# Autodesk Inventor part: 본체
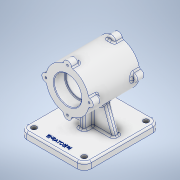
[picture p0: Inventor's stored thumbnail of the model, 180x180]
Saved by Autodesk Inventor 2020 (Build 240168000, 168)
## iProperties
Created: 2022-11
Part Number: 본체
Material: 알루미늄 6061
Document SubType Name: Modeling
Designer: Owner
Density: 2.7 g/cm^3
Appearance: 알루미늄 - 평지
Mass: 1215.39 g
Surface Area: 796.917 cm^2
Volume: 450.145 cm^3
Author: Owner
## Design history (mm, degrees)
sketch "스케치1"
  geometry: C1 r 7 at (0, 37); C2 r 7 at (37, 0); C3 r 7 at (0, -37); C4 r 7 at (-37, 0); A1 r 37 centre (0, 0) between (0, 37) and (37, 0); 9 further points
  constraints: 5 centre point, 4 point on circle, 2 horizontal alignment, 2 vertical alignment, 1 coincident
  dimensions: "d0" = 74 diameter of A1; "d1" = 14 diameter of C1; "d2" = 14 diameter of C2; "d3" = 14 diameter of C3; "d4" = 14 diameter of C4
extrude "돌출1" new body sketch "스케치1" stored distance "d5" = 87; taper "d6" = 0 deg
sketch "스케치2"
  geometry: A1 r 37 centre (0, 0) between (36.338, 6.969) and (6.969, 36.338) reference; 2 further points
  constraints: 1 coincident
hole "구멍1" sketch "스케치2" at (0, 0) diameter "d7" = 42; stored, may be unused: countersink angle "d11" = 90 deg, drill point angle "d13" = 0 deg; dims "d8" = 8, "d9" = 47, "d10" = 19, "d12" = 68
sketch "스케치3"
  geometry: A1 r 37 centre (0, 0) between (36.338, 6.969) and (6.969, 36.338) reference; 2 further points
  constraints: 1 coincident
hole "구멍2" sketch "스케치3" at (0, 0) diameter "d14" = 47; stored, may be unused: countersink angle "d18" = 90 deg, drill point angle "d20" = 0 deg; dims "d15" = 8, "d16" = 47, "d17" = 19, "d19" = 19
sketch "스케치4"
  geometry: 1 further point
node "작업 평면1"
sketch "스케치11"
  geometry: L1 (-37, -43.5)-(37, -43.5) reference; L2 (37, 43.5)-(-37, 43.5) reference; L3 (-55, -60)-(55, -60); L4 (55, -60)-(55, 70); L5 (55, 70)-(-55, 70); L6 (-55, 70)-(-55, -60); 2 further points
  constraints: 8 end point, 2 parallel, 1 horizontal, 1 midpoint, 1 perpendicular, 1 vertical alignment
  dimensions: "d49" = 130 distance of L3.end L4.end; "d50" = 70 distance from line of L5 point (0, 0); "d51" = 110 distance of L3.start L3.end
extrude "돌출3" join sketch "스케치11" distance "d52" = 12; taper "d53" = 0 deg
fillet "모깎기2" dims "d54" = 12
sketch "스케치12"
  geometry: 1 further point
sketch "스케치13"
  geometry: A1 r 12 centre (-43, -58) between (-55, -58) and (-43, -70) reference; 2 further points
  constraints: 1 coincident
hole "구멍6" sketch "스케치13" at (-43, -58) diameter "d55" = 9; stored, may be unused: countersink angle "d59" = 90 deg, drill point angle "d61" = 0 deg; dims "d56" = 8, "d57" = 47, "d58" = 19, "d60" = 19
sketch "스케치14"
  geometry: A1 r 12 centre (43, -58) between (43, -70) and (55, -58) reference; 2 further points
  constraints: 1 coincident
hole "구멍7" sketch "스케치14" at (43, -58) diameter "d62" = 9; stored, may be unused: countersink angle "d66" = 90 deg, drill point angle "d68" = 0 deg; dims "d63" = 8, "d64" = 47, "d65" = 19, "d67" = 19
sketch "스케치15"
  geometry: A1 r 12 centre (-43, 48) between (-43, 60) and (-55, 48) reference; 2 further points
  constraints: 1 coincident
hole "구멍8" sketch "스케치15" at (-43, 48) diameter "d69" = 9; stored, may be unused: countersink angle "d73" = 90 deg, drill point angle "d75" = 0 deg; dims "d70" = 8, "d71" = 47, "d72" = 19, "d74" = 19
sketch "스케치16"
  geometry: A1 r 12 centre (43, 48) between (55, 48) and (43, 60) reference; 2 further points
  constraints: 1 coincident
hole "구멍9" sketch "스케치16" at (43, 48) diameter "d76" = 9; stored, may be unused: countersink angle "d80" = 90 deg, drill point angle "d82" = 0 deg; dims "d77" = 8, "d78" = 47, "d79" = 19, "d81" = 19
sketch "스케치17"
  geometry: L1 (-43, -70)-(43, -70) reference; L2 (41, -70)-(25.336, -26.964); L3 (55, -82)-(55, -70) reference; L4 (-41, -70)-(-25.336, -26.964); L5 (-55, -70)-(-55, -82) reference; A1 r 37 centre (0, 0) between (25.336, -26.964) and (-25.336, -26.964) reference; 1 further point
  constraints: 4 end point, 2 point on circle, 2 point on line
  dimensions: "d83" = 14 distance from line of L3 L2.start; "d84" = 110 deg angle of L1 L2; "d85" = 14 distance from line of L5 L4.start; "d86" = 110 deg angle of L1 L4
extrude "돌출4" join sketch "스케치17" stored distance "d87" = 10; taper "d88" = 0 deg
sketch "스케치18"
  geometry: L1 (-70, -48)-(-70, 58) reference; L2 (-70, 5)-(-70, -5) reference; L3 (-26.964, 5)-(-70, 5) reference; L4 (-26.964, -5)-(-26.964, 5) reference; L5 (-70, -5)-(-26.964, -5) reference; L6 (-70, 20)-(-47.493, 20); 1 further point
  constraints: 2 end point, 1 horizontal, 1 point on line
  dimensions: "d89" = 20 vertical distance of point (0, 0) L6.start
feature "리브1" sketch "스케치18" dims "d90" = 1, "d91" = 10, "d92" = 0, "d93" = 0, "d94" = 1, "d95" = 1
sketch "스케치19"
  geometry: C1 r 23.5 at (0, 0) reference; C2 r 7 at (0, 37); C3 r 7 at (37, 0); C4 r 7 at (-37, 0); C5 r 7 at (0, -37); A1 r 37 centre (0, 0) between (-5, -36.661) and (5, -36.661) reference; A2 r 37 centre (0, 0) between (0, 37) and (37, 0) reference; A3 r 37 centre (0, 0) between (-5, -36.661) and (5, -36.661) reference; 9 further points
  constraints: 4 centre point, 4 point on circle, 2 horizontal alignment, 1 vertical alignment
  dimensions: "d96" = 14 diameter of C2; "d97" = 14 diameter of C3; "d98" = 14 diameter of C4; "d100" = 14 diameter of C5
extrude "돌출5" join sketch "스케치19" distance "d101" = 14; taper "d102" = 0 deg
sketch "스케치20"
  geometry: A1 r 7 centre (0, 37) between (6.969, 36.338) and (-6.969, 36.338) reference; 2 further points
  constraints: 1 coincident
hole "구멍10" sketch "스케치20" at (0, 37) diameter "d103" = 3.242; stored, may be unused: countersink angle "d107" = 90 deg, drill point angle "d109" = 118 deg; dims "d104" = 8, "d105" = 47, "d106" = 19, "d108" = 10
sketch "스케치21"
  geometry: A1 r 7 centre (0, 37) between (6.969, 36.338) and (-6.969, 36.338) reference; 2 further points
  constraints: 1 coincident
hole "구멍11" sketch "스케치21" at (0, 37) diameter "d113" = 3.242; stored, may be unused: countersink angle "d117" = 90 deg, drill point angle "d119" = 118 deg; dims "d114" = 8, "d115" = 47, "d116" = 19, "d118" = 10
fillet "모깎기3" dims "d123" = 3
fillet "모깎기4" dims "d124" = 3
fillet "모깎기5" dims "d125" = 3
fillet "모깎기6" dims "d126" = 3
fillet "모깎기7" dims "d127" = 3
fillet "모깎기8" dims "d128" = 3
fillet "모깎기9" dims "d129" = 3
fillet "모깎기10" dims "d130" = 3
fillet "모깎기11" dims "d131" = 3
fillet "모깎기12" dims "d132" = 3
fillet "모깎기13" dims "d133" = 3
fillet "모깎기14" dims "d134" = 3
fillet "모깎기15" dims "d135" = 3
fillet "모깎기16" dims "d136" = 3
fillet "모깎기17" dims "d137" = 3
fillet "모깎기18" dims "d138" = 3
fillet "모깎기19" dims "d139" = 3
fillet "모깎기20" dims "d140" = 3
sketch "스케치22"
  geometry: L1 (-43, -70)-(43, -70) reference; 3 further points
  constraints: 1 midpoint, 1 vertical alignment, 1 other
  dimensions: "d141" = 12 distance from line of L1 point (0, -58)
feature "엠보싱1" sketch "스케치22" dims "d14" = 47, "d142" = 0.5, "d143" = 0
chamfer "모따기1" distance "d144" = 1; stored, may be unused: second distance "d145" = 2, angle "d146" = 45 deg
fillet "모깎기21" dims "d147" = 1
node "솔리드1"
mirror "미러1"
mirror "미러2"
pattern_circular "원형 패턴1" dims angle "d111" = 360 deg
pattern_circular "원형 패턴2" dims angle "d121" = 360 deg
node "투영된 루프4"
node "투영된 루프5"
node "투영된 루프6"
feature "A9D066F2-1C7D-4E18-AEED-F7BC21143FA4" dims "d7" = 42, "d8" = 8, "d9" = 47, "d10" = 19, "d11" = 90 deg, "d12" = 68, "d13" = 0
other parameters: "d21" = -82
